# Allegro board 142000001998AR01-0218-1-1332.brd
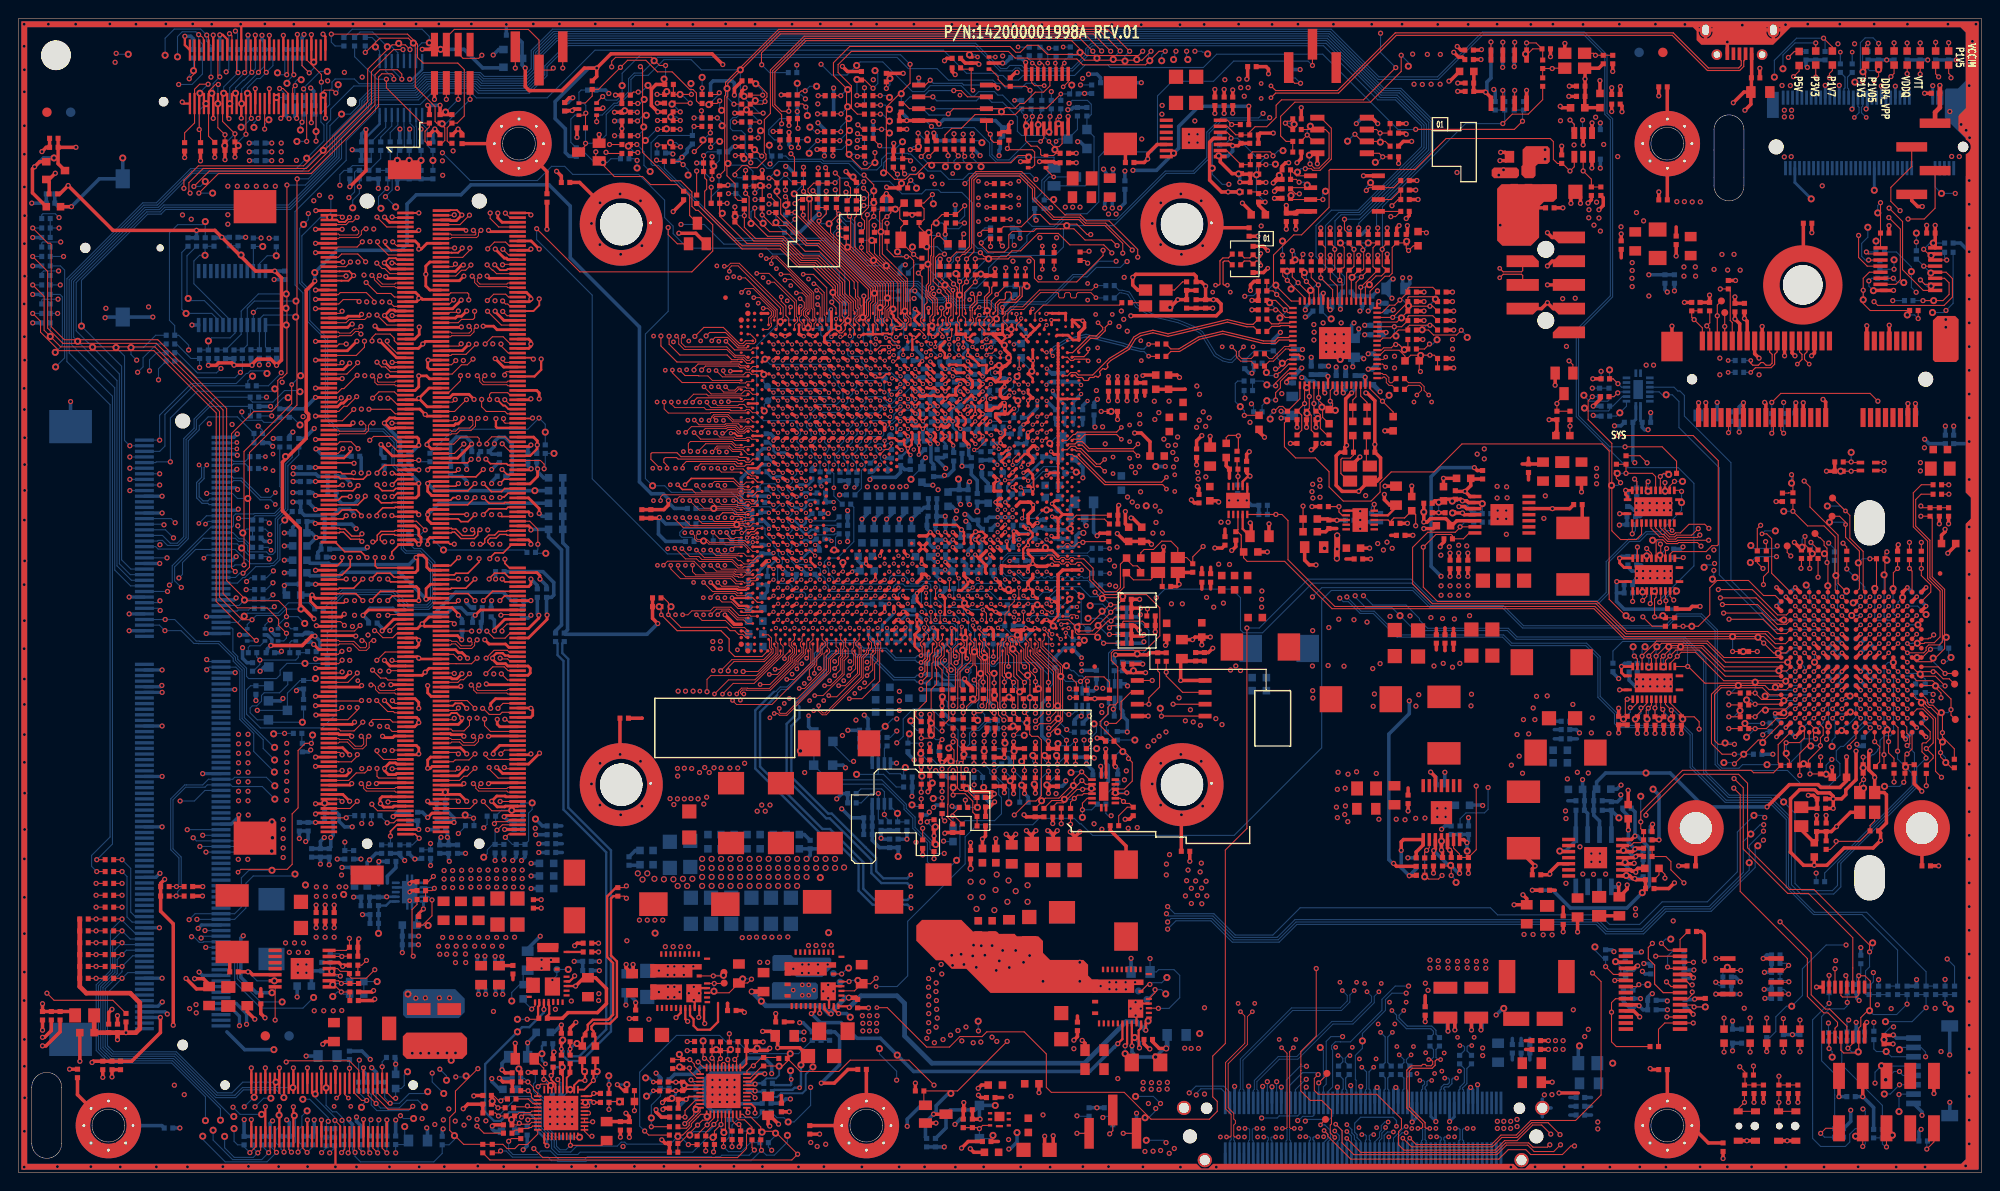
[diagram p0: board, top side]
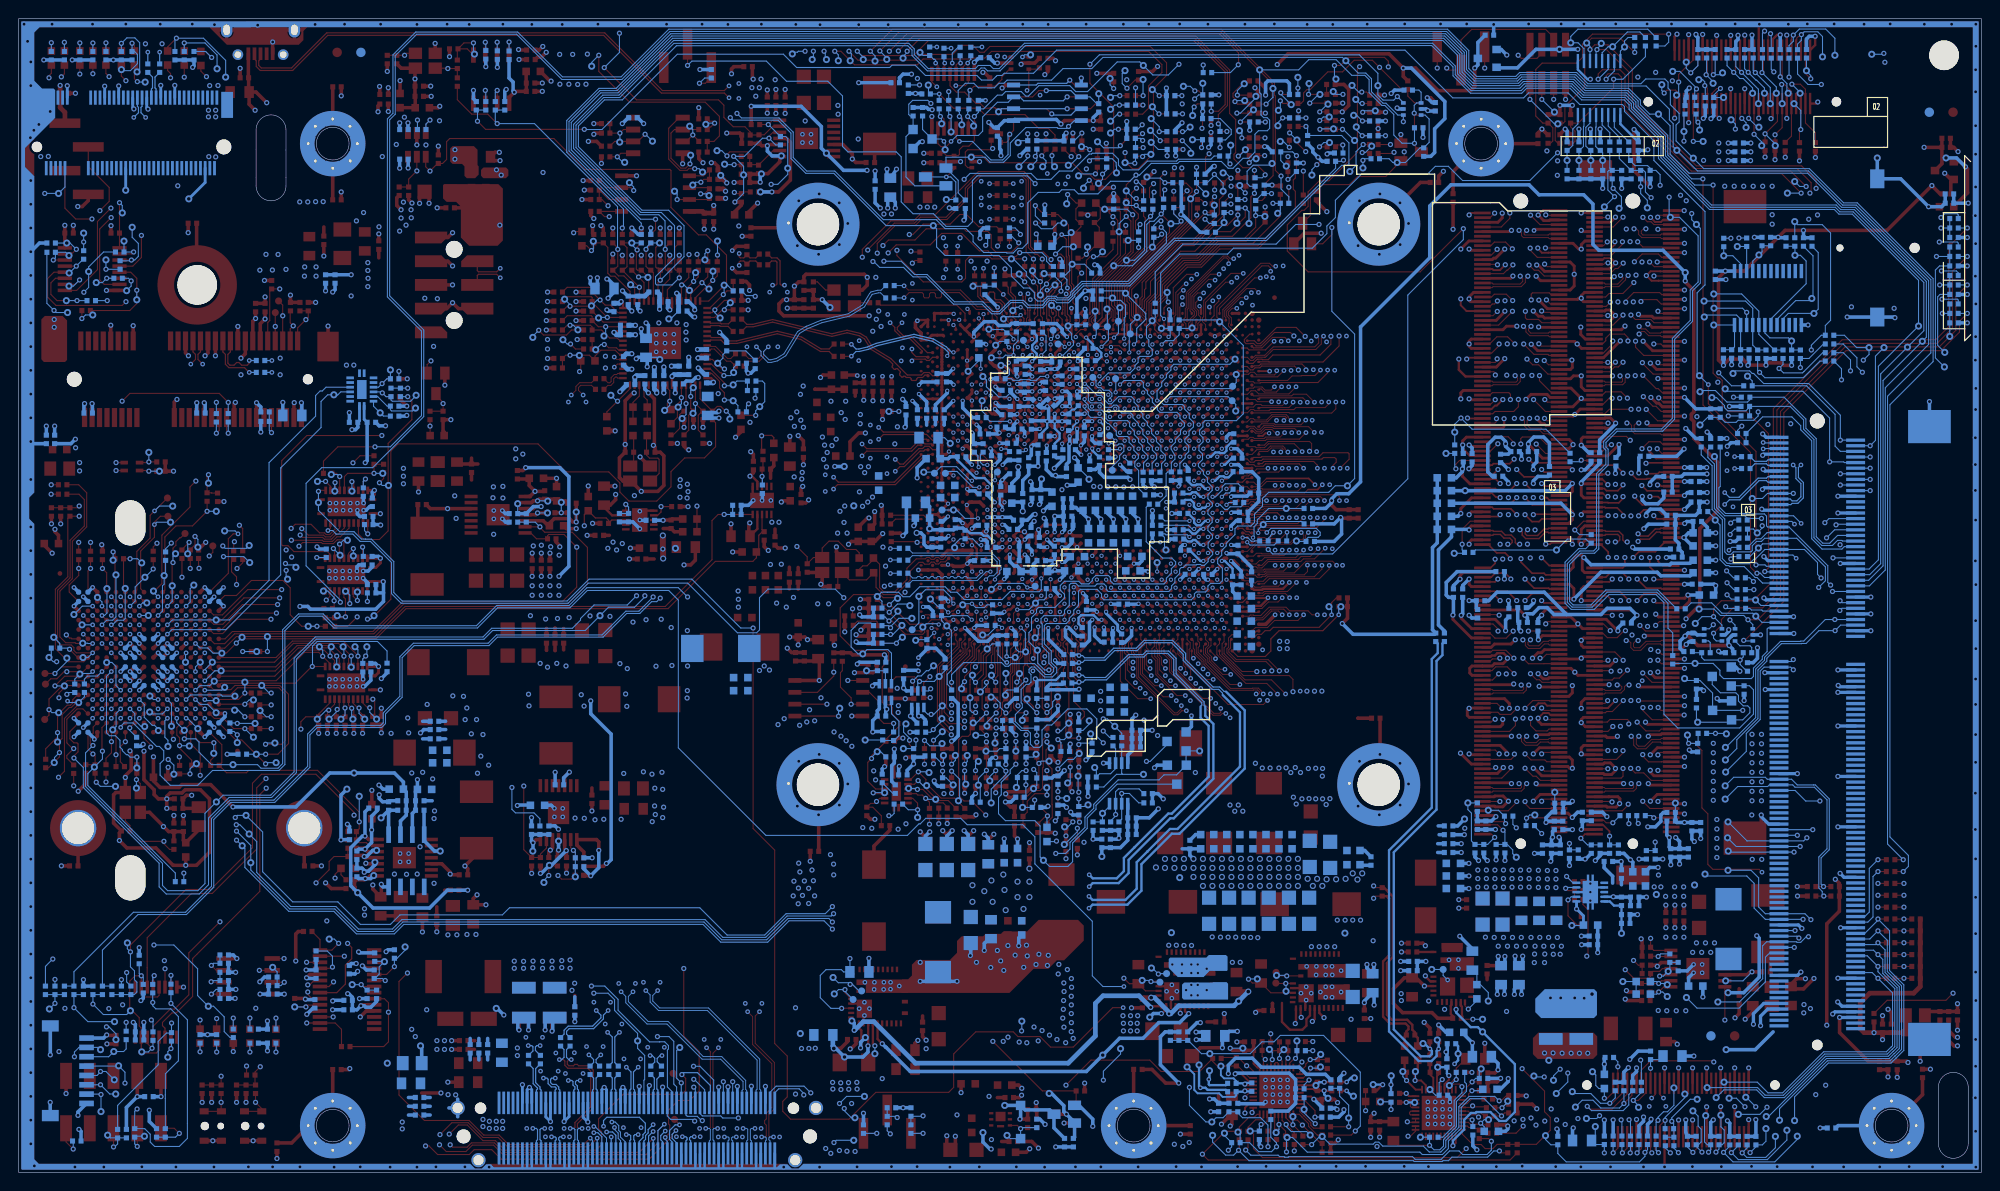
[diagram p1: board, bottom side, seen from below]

Outline 210 x 123.5 mm; copper layers: TOP, G2, S3, G4, S5, V6, V7, S8, G9, S10, G11, BOTTOM. Coordinates in mm from the lower left corner of the outline.
Outline path: 0,123.5 0,0 210,0 210,123.5 0,123.5 ; 1.4,9.1 1.4,3.1 arc(3,1.5) 4.6,3.1 4.6,9.1 arc(3,10.7) 1.4,9.1 ; 7.85,5 arc(9.6,6.75) 11.35,5 arc(9.6,3.25) 7.85,5 ; 51.78,110.12 arc(53.87,111.84) 55.14,109.45 arc(53.53,108.37) 51.91,109.45 arc(51.81,109.78) 51.78,110.12 ; 62.22,101.5 arc(64.47,103.75) 66.73,101.5 arc(64.47,99.25) 62.22,101.5 ; 62.22,41.5 arc(64.47,43.75) 66.73,41.5 arc(64.47,39.25) 62.22,41.5 ; 88.95,5 arc(90.7,6.75) 92.45,5 arc(90.7,3.25) 88.95,5 ; 122.23,101.5 arc(124.47,103.75) 126.72,101.5 arc(124.47,99.25) 122.23,101.5 ; 122.23,41.5 arc(124.47,43.75) 126.72,41.5 arc(124.47,39.25) 122.23,41.5 ; 174.65,5 arc(176.4,6.75) 178.15,5 arc(176.4,3.25) 174.65,5 ; 174.79,109.45 arc(176.06,111.84) 178.15,110.12 arc(178.12,109.78) 178.02,109.45 arc(176.4,108.37) 174.79,109.45 ; 177.75,36.85 arc(179.45,38.55) 181.15,36.85 arc(179.45,35.15) 177.75,36.85 ; 181.4,111.6 arc(183,113.2) 184.6,111.6 184.6,105.6 arc(183,104) 181.4,105.6 181.4,111.6 ; 188.8,95 arc(190.9,97.1) 193,95 arc(190.9,92.9) 188.8,95 ; 196.45,70.32 arc(198.05,71.92) 199.65,70.32 199.65,68.72 arc(198.05,67.12) 196.45,68.72 196.45,70.32 ; 196.45,32.32 arc(198.05,33.92) 199.65,32.32 199.65,30.72 arc(198.05,29.12) 196.45,30.72 196.45,32.32 ; 201.95,36.85 arc(203.65,38.55) 205.35,36.85 arc(203.65,35.15) 201.95,36.85

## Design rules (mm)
net group DIFF_10G_KR_C_RX0_: nets 10G_KR_C_RX0_N 10G_KR_C_RX0_P
net group DIFF_10G_KR_C_RX1_: nets 10G_KR_C_RX1_N 10G_KR_C_RX1_P
net group DIFF_10G_KR_RX0_: nets 10G_KR_RX0_N 10G_KR_RX0_P
net group DIFF_10G_KR_RX1_: nets 10G_KR_RX1_N 10G_KR_RX1_P
net group DIFF_10G_KR_TX0_: nets 10G_KR_TX0_N 10G_KR_TX0_P
net group DIFF_10G_KR_TX1_: nets 10G_KR_TX1_N 10G_KR_TX1_P
net group DIFF_CLK_100M_XDPCPU_: nets CLK_100M_XDPCPU_N CLK_100M_XDPCPU_P
net group DIFF_CLK_100M_XDPCPU_R_: nets CLK_100M_XDPCPU_R_N CLK_100M_XDPCPU_R_P
net group DIFF_CS1_VDDQ_CH01: nets CSN1_VDDQ_CH01 CSP1_VDDQ_CH01
net group DIFF_CS1_VDDQ_CH01_R: nets CSN1_VDDQ_CH01_R CSP1_VDDQ_CH01_R
net group DIFF_DDR0_CLK_D_1: nets DDR0_CLK_DN_1 DDR0_CLK_DP_1
net group DIFF_DDR0_CLK_D_3: nets DDR0_CLK_DN_3 DDR0_CLK_DP_3
net group DIFF_DDR1_CLK_D_1: nets DDR1_CLK_DN_1 DDR1_CLK_DP_1
net group DIFF_DDR1_CLK_D_3: nets DDR1_CLK_DN_3 DDR1_CLK_DP_3
net group DIFF_MAC_SGMII_RX_: nets MAC_SGMII_RX_N MAC_SGMII_RX_P
net group DIFF_MAC_SGMII_TX_: nets MAC_SGMII_TX_N MAC_SGMII_TX_P
net group DIFF_MGMT_MAC_RX0: nets PCIE2_MGMT_MAC_RX0_N_R PCIE2_MGMT_MAC_RX0_P_R
net group DIFF_PCIE2_MGMT_MAC_RX0_: nets PCIE2_MGMT_MAC_RX0_N PCIE2_MGMT_MAC_RX0_P
net group DIFF_PCIE2_MGMT_MAC_TX0_: nets PCIE2_MGMT_MAC_TX0_N PCIE2_MGMT_MAC_TX0_P
net group DIFF_PCIE3_100G_C_TX_D_0: nets PCIE3_100G_C_TX_DN_0 PCIE3_100G_C_TX_DP_0
net group DIFF_PCIE3_100G_C_TX_D_1: nets PCIE3_100G_C_TX_DN_1 PCIE3_100G_C_TX_DP_1
net group DIFF_PCIE3_100G_C_TX_D_2: nets PCIE3_100G_C_TX_DN_2 PCIE3_100G_C_TX_DP_2
net group DIFF_PCIE3_100G_C_TX_D_3: nets PCIE3_100G_C_TX_DN_3 PCIE3_100G_C_TX_DP_3
net group DIFF_PCIE3_100G_RX_D_0: nets PCIE3_100G_RX_DN_0 PCIE3_100G_RX_DP_0
net group DIFF_PCIE3_100G_RX_D_1: nets PCIE3_100G_RX_DN_1 PCIE3_100G_RX_DP_1
net group DIFF_PCIE3_100G_RX_D_2: nets PCIE3_100G_RX_DN_2 PCIE3_100G_RX_DP_2
net group DIFF_PCIE3_100G_RX_D_3: nets PCIE3_100G_RX_DN_3 PCIE3_100G_RX_DP_3
net group DIFF_PCIE3_100G_TX_D_0: nets PCIE3_100G_TX_DN_0 PCIE3_100G_TX_DP_0
net group DIFF_PCIE3_100G_TX_D_1: nets PCIE3_100G_TX_DN_1 PCIE3_100G_TX_DP_1
net group DIFF_PCIE3_100G_TX_D_2: nets PCIE3_100G_TX_DN_2 PCIE3_100G_TX_DP_2
net group DIFF_PCIE3_100G_TX_D_3: nets PCIE3_100G_TX_DN_3 PCIE3_100G_TX_DP_3
net group DIFF_PCIE_BMM_RX_: nets PCIE_BMM_RX_N PCIE_BMM_RX_P
net group DIFF_PCIE_BMM_TX_: nets PCIE_BMM_TX_N PCIE_BMM_TX_P
net group DIFF_PCIE_BMM_TX_C_: nets PCIE_BMM_TX_C_N PCIE_BMM_TX_C_P
net group DIFF_PCIE_CLK_B2B_CONN: nets PCIE_CLK_B2B_CONN_N PCIE_CLK_B2B_CONN_P
net group DIFF_PCIE_CLK_BMM_: nets PCIE_CLK_BMM_N PCIE_CLK_BMM_P
net group DIFF_PCIE_CLK_MAC: nets PCIE_CLK_MAC_N_R PCIE_CLK_MAC_P_R
net group DIFF_PCIE_CLK_MAC_: nets PCIE_CLK_MAC_N PCIE_CLK_MAC_P
net group DIFF_PCIE_CLK_R_B2B_CONN: nets PCIE_CLK_R_B2B_CONN_N PCIE_CLK_R_B2B_CONN_P
net group DIFF_PCIE_CLK_R_BMM_: nets PCIE_CLK_R_BMM_N PCIE_CLK_R_BMM_P
net group DIFF_PCIE_OOB_RX_: nets PCIE_OOB_RX_N PCIE_OOB_RX_P
net group DIFF_PCIE_OOB_TX_: nets PCIE_OOB_TX_N PCIE_OOB_TX_P
net group DIFF_PCIE_OOB_TX_C_: nets PCIE_OOB_TX_C_N PCIE_OOB_TX_C_P
net group DIFF_PD_CPU_TSTCLK_D: nets PD_CPU_TSTCLK_DN PD_CPU_TSTCLK_DP
net group DIFF_PD_TSTCLK_SC_D: nets PD_TSTCLK_SC_DN PD_TSTCLK_SC_DP
net group DIFF_RP_1.05V_R_SENSE_: nets RP_1.05V_R_SENSE_N RP_1.05V_R_SENSE_P
net group DIFF_RP_1.05V_SENSE_: nets RP_1.05V_SENSE_N RP_1.05V_SENSE_P
net group DIFF_RP_1.8V_SENSE_: nets RP_1.8V_SENSE_N RP_1.8V_SENSE_P
net group DIFF_RP_1.8V_SENSE__R: nets RP_1.8V_SENSE_N_R RP_1.8V_SENSE_P_R
net group DIFF_RP_CLKIN_GND_1_: nets RP_CLKIN_GND_1_N RP_CLKIN_GND_1_P
net group DIFF_RP_CLKIN_GND_2_: nets RP_CLKIN_GND_2_N RP_CLKIN_GND_2_P
net group DIFF_RP_CLKIN_GND_3_: nets RP_CLKIN_GND_3_N RP_CLKIN_GND_3_P
net group DIFF_RP_CLKIN_GND_4: nets RP_CLKIN_GND_N4 RP_CLKIN_GND_P4
net group DIFF_SATA3_C_RX0_: nets SATA3_C_RX0_N SATA3_C_RX0_P
net group DIFF_SATA3_C_RX1_: nets SATA3_C_RX1_N SATA3_C_RX1_P
net group DIFF_SATA3_C_TX0_: nets SATA3_C_TX0_N SATA3_C_TX0_P
net group DIFF_SATA3_C_TX1_: nets SATA3_C_TX1_N SATA3_C_TX1_P
net group DIFF_SATA3_RX0_: nets SATA3_RX0_N SATA3_RX0_P
net group DIFF_SATA3_RX1_: nets SATA3_RX1_N SATA3_RX1_P
net group DIFF_SATA3_TX0_: nets SATA3_TX0_N SATA3_TX0_P
net group DIFF_SATA3_TX1_: nets SATA3_TX1_N SATA3_TX1_P
net group DIFF_SGM_RX: nets MAC_SGMII_RX_N_R MAC_SGMII_RX_P_R
net group DIFF_TP_PE_HSCLK_D: nets TP_PE_HSCLK_DN TP_PE_HSCLK_DP
net group DIFF_TP_TEST_PE_DFX_D: nets TP_TEST_PE_DFX_DN TP_TEST_PE_DFX_DP
net group DIFF_TP_USB2_PLLMON_D: nets TP_USB2_PLLMON_DN TP_USB2_PLLMON_DP
net group DIFF_USB2_DEBUG_D: nets USB2_DEBUG_DN USB2_DEBUG_DP
net group DIFF_USB2_EUSB_D: nets USB2_EUSB_DN USB2_EUSB_DP
net group DIFF_USB2_FRONT_D: nets USB2_FRONT_DN USB2_FRONT_DP
net group DIFF_VDDQ_CPU_SEN_: nets VDDQ_CPU_SEN_N VDDQ_CPU_SEN_P
net group DIFF_VDDQ_CPU_SEN__R: nets VDDQ_CPU_SEN_N_R VDDQ_CPU_SEN_P_R
net group DIFF_VDDQ_TSEN_: nets VDDQ_TSEN_N VDDQ_TSEN_P
net group PCIE2_MGMT_MAC_C_TX0_: nets PCIE2_MGMT_MAC_C_TX0_N PCIE2_MGMT_MAC_C_TX0_P
net group PCIE_CLK_R_MAC_: nets PCIE_CLK_R_MAC_N PCIE_CLK_R_MAC_P
net group USB2: nets USB2_DN_3 USB2_DP_3
net group CLS_CLK: nets 1PPS_CPU BIOS_SPI_C_CLK BIOS_SPI_CLK BIOS_SPI_CLK_R CLK_33M_BMM CLK_33M_BMM_R CLK_33M_CPLD CLK_33M_LPC CLK_33M_LPC_PORT80 CLK_33M_LPC_TPM CLK_33M_R_CPLD CLK_33M_R_LPC CLK_33M_R_TPM CLK_33M_TPM CLK_50M CLK_50M_R CLK_BUF_50M_BMM CLK_BUF_50M_BMM_R CLK_M2_SUSCLK CPLD_CLK_25M CPLD_CLK_25M_R NIC1_NCSI_CLKIN_R RP_LPC_LCLK RP_LPC_R_LCLK RP_SVID_R_CLK SPI_10GBE_CLK SPI_10GBE_CLK_LVC3V3 SPI_10GBE_CLK_LVC3V3_R SPI_10GBE_CLK_R SVID_CLK SVID_CLK_DDR_R SVID_CLK_VCORE
net group CLS_DDR_POWER: nets P1V2_VDDQ
net group CLS_POWER: nets AGND_V3P3A DDR4_VPP_SW GND_SCREW1 GND_SCREW2 GND_SCREW3 GND_SCREW4 GND_SCREW5 P1V05_PCH_FLT P3V3_STBY_CLKBUF P3V3_STBY_OSC P5V_B P5V_CONN PS_12V_LVIN3 RP_3.3V_LVCC SW_VDDQ_CH01 V1P5_FB V1P5_SS V1P8A_EN V1P35_FB V1P35_SS V3P3_EN V3P3_PCH_EN V3P3_PCH_EN_N V3P3_R V3P3_SF100 V3P3_SPI V3P3_SS V3P3_SW V3P3_VBST V3P3_VREG V3P3A_EN V3P3A_R V3P3A_SS V3P3A_VBST V3P3A_VREG V5A_SS V5A_SW V5A_VBST V5A_VO V5A_VREG V12A_V5A VCC_EUSB VCCAXCK_DCB VCCGBE_FLT VCCIN_P1V05_VCC
net group CLS_S12: nets MAC_MDC0 RP_DDR_R_I2C_SCL SMB_9548_SCL0 SMB_9548_SCL1 SMB_PCU_CLK_P3V3 SMB_PCU_CLK_P3V3_SWITCH_R SUSCLK_32K_CPLD
net group XDP_CPU_MBP: nets XDP_CPU_MBP<2> XDP_CPU_MBP<3> XDP_CPU_MBP<4> XDP_CPU_MBP<5> XDP_CPU_MBP<6> XDP_CPU_MBP<7>

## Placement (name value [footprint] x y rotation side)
BA1  AAA-BAT-046-K03  [BATTERY_14D8_2SP_15D5W10D39L]  11.13 98.96 270 bottom
C1  0.1uF/10V  [CC0402]  185.85 117.17 90 top
C2  22uF/16V  [CC0805]  186.36 115.65 90 top
C3  0.1uF  [CC0402]  175.94 116.2 270 top
C4  100uF/6.3V  [CC1206]  123.83 115.88 0 top
C5  100uF/6.3V  [CC1206]  125.99 115.88 0 top
C6  1uF/6.3V  [CC0402]  170.91 114.35 90 top
C7  0.1uF/16V  [CC0402]  170.91 115.4 90 top
C8  10uF/6.3V  [CC0402]  127.99 114.66 0 top
C9  10nF/50V  [CC0402]  128.98 114.66 180 top
C10  0.1uF/16V  [CC0402]  129.9 114.66 180 top
C11  0.1uF/16V  [CC0402]  58.43 114.07 180 top
C12  0.1uF  [CC0402]  191.41 101.6 90 top
C13  0.1uF/16V  [CC0402]  94.23 112.12 0 top
C14  1uF/6.3V  [CC0402]  3.76 110.69 90 top
C15  0.1uF  [CC0402]  47.44 110.58 180 top
C16  0.1uF/16V  [CC0402]  155.19 119.13 90 top
C17  1uF/6.3V  [CC0402]  155.19 120.14 90 top
C18  0.1uF/16V  [CC0402]  155.23 115.72 270 top
C19  1uF/6.3V  [CC0402]  155.23 116.61 270 top
C20  1uF/6.3V  [CC0402]  132.18 110.16 90 top
C21  1uF/6.3V  [CC0402]  3.76 109.73 90 top
C22  @10pF  [CC0402]  163.45 120.27 270 top
C23  0.1uF/25V  [CC0402]  118.87 108.1 90 top
C24  10pF/50V  [CC0402]  130.84 107.37 180 top
C25  0.1uF  [CC0402]  131.65 100.66 180 top
C26  10nF  [CC0402]  104.85 105.84 270 top
C27  22uF/16V  [CC0805]  116.74 105.41 0 top
C28  22uF/16V  [CC0805]  116.74 105.41 180 bottom
C29  0.1uF/16V  [CC0402]  118.36 105.69 180 bottom
C30  0.1uF/16V  [CC0402]  183.64 92.57 180 top
C31  0.1uF/16V  [CC0402]  184.65 92.57 180 top
C32  10nF  [CC0402]  104.85 104.57 270 top
C33  22uF/16V  [CC0805]  113.77 104.39 90 top
C34  3300pF  [CC0402]  132.67 104.32 0 top
C35  0.1uF  [CC0402]  56.52 104.31 0 top
C36  0.1uF  [CC0402]  175.95 104.1 270 top
C37  10nF  [CC0402]  104.85 103.3 270 top
C38  15pF  [CC0402]  94.9 102.13 180 top
C39  15pF  [CC0402]  96.34 102.13 180 top
C40  10nF  [CC0402]  104.85 102.03 270 top
C41  @10pF  [CC0402]  161.04 114.17 0 bottom
C42  0.1uF  [CC0402]  124.85 34.37 270 top
C51  0.1uF  [CC0402]  125.98 94.87 180 top
C52  0.1uF  [CC0402]  127 92.96 180 top
C54  0.1uF/16V  [CC0402]  202.56 81.28 90 bottom
C55  1uF/6.3V  [CC0402]  192.89 39.98 90 top
C57  0.22uF  [CC0402]  122.3 88.67 90 top
C58  0.1uF/16V  [CC0402]  190.5 81.28 90 bottom
C59  0.1uF/16V  [CC0402]  192.89 38.96 90 top
C60  0.22uF  [CC0402]  122.3 87.35 90 top
C61  22uF/16V  [CC0805]  180.72 81.03 270 bottom
C63  22uF6.3V  [CC0603]  205.62 77.37 270 top
C64  1uF/6.3V  [CC0402]  206.15 78.46 180 bottom
C65  0.1uF/16V  [CC0402]  207.04 78.46 180 bottom
C66  1uF/6.3V  [CC0402]  192.38 36.93 180 top
C67  0.1uF/16V  [CC0402]  193.4 36.93 180 top
C68  22uF/6.3V  [CC0603]  121.67 84.59 0 top
C69  22uF/6.3V  [CC0603]  123.04 84.59 0 top
C70  22uF/6.3V  [CC0603]  192.13 34.52 0 top
C74  1uF/6.3V  [CC0402]  120.49 84.07 0 top
C75  1uF/6.3V  [CC0402]  119.58 84.07 0 top
C76  0.1uF/16V  [CC0402]  117.57 84.07 0 top
C77  0.1uF/16V  [CC0402]  118.59 84.07 0 top
C78  0.1uF/16V  [CC0402]  116.61 84.07 0 top
C81  4.7uF/6.3V  [CC0603]  149.06 71.58 0 top
C82  10uF/6.3V  [CC0402]  147.87 68.19 90 top
C83  22uF/6.3V  [CC0603]  206.5 67.31 90 top
C84  22uF/16V  [CC0805]  147.37 72.44 180 top
C87  0.1uF/16V  [CC0402]  126.03 76.99 0 top
C88  47uF/6.3V  [CC0805]  127.49 76.62 180 top
C89  680pF/50V  [CC0402]  131.39 75.66 180 top
C90  @0.1uF/16V  [CC0402]  130 75.28 270 top
C91  0.1uF/16V  [CC0402]  143.35 65.66 90 top
C92  22uF/6.3V  [CC0603]  142.82 66.82 90 top
C93  22uF/6.3V  [CC0603]  127.45 72.65 0 top
C94  0.1uF/16V  [CC0402]  126.29 72.12 0 top
C95  @0.1uF/16V  [CC0402]  140.19 69.37 0 top
C96  680pF/50V  [CC0402]  139.68 71.27 270 top
C97  47uF/6.3  [CC0805]  138.62 66.93 270 top
C98  0.1uF  [CC0402]  66.67 70.48 0 top
C99  22uF/16V  [CC0805]  132.77 68.1 90 top
C100  0.1uF/16V  [CC0402]  171.2 48.36 180 top
C101  10uF/6.3V  [CC0402]  129.07 67.59 0 top
C102  4.7uF/6.3V  [CC0603]  131.83 66.41 270 top
C103  12pF/1%  [CC0402]  125.63 64.69 0 top
C104  1uF/6.3V  [CC0402]  126.6 63.63 180 top
C105  1uF/6.3V  [CC0402]  127.54 63.63 180 top
C106  47uF  [CC0603]  128.73 63.12 180 top
C107  47uF  [CC0603]  130.1 63.12 180 top
C108  12pF/1%  [CC0402]  122.81 62.71 90 top
C109  22uF/6.3V  [CC0603]  194.82 42.29 270 top
C110  0.1uF/25V  [CC0402]  162.41 31.85 90 top
C111  22uF/16V  [CC0805]  124.46 56.01 180 top
C112  0.1uF/16V  [CC0402]  125.93 55.19 180 top
C113  1uF/ 6.3V  [CC0402]  126.87 55.19 180 top
C114  0.1uF/16V  [CC0402]  118.65 54.41 270 top
C115  22uF/6.3V  [CC0603]  164.95 43.84 270 bottom
C116  22uF/6.3V  [CC0603]  164.95 45.19 270 bottom
C117  10uF/6.3V  [CC0402]  165.51 46.41 270 bottom
C118  0.1uF/16V  [CC0402]  165.26 27 0 top
C119  10nF/50V  [CC0402]  165.51 47.4 90 bottom
C120  0.1uF/16V  [CC0402]  165.51 48.29 90 bottom
C121  22uF/16V  [CC0805]  166.8 28.35 0 top
C123  22uF/16V  [CC0805]  171.27 28.47 180 top
C124  0.1uF  [CC0402]  58.52 105.97 90 top
C125  220uF/4V  [CAP_6D4_2SP_4D3W7D3L2D1H]  87.78 45.92 0 top
C126  0.1uF  [CC0402]  204.1 32.81 90 top
C127  0.1uF  [CC0402]  178.97 32.8 270 top
C128  0.1uF/16V  [CC0402]  116.76 44.48 90 top
C129  3300pF  [CC0402]  174.32 34.7 270 top
C130  @10pF/50V  [CC0402]  136.78 112.78 90 top
C131  220uF/4V  [CAP_6D4_2SP_4D3W7D3L2D1H]  76.23 38.45 270 top
C132  220uF/4V  [CAP_6D4_2SP_4D3W7D3L2D1H]  81.56 38.45 270 top
C133  220uF/4V  [CAP_6D4_2SP_4D3W7D3L2D1H]  86.79 38.45 270 top
C134  100uF/6.3V  [CC1206]  71.75 37.24 180 top
C135  100uF/6.3V  [CC1206]  161.08 64.74 180 top
C136  100uF/6.3V  [CC1206]  158.84 64.74 180 top
C137  100uF/6.3V  [CC1206]  156.67 64.74 180 top
C138  0.1uF  [CC0402]  64.79 48.61 270 top
C139  0.1uF  [CC0402]  102.49 65.48 90 bottom
C140  10uF/6.3V  [CC0402]  154.08 65.07 180 top
C141  10nF/50V  [CC0402]  153.16 65.07 0 top
C142  0.1uF/16V  [CC0402]  155.06 65.07 0 top
C143  22uF/6.3V  [CC0603]  104.55 33.9 180 top
C144  22uF/6.3V  [CC0603]  104.16 26.17 0 top
C145  22uF/6.3V  [CC0603]  102.68 26.17 0 top
C146  22uF/6.3V  [CC0603]  103.12 33.9 180 top
C147  47uF/6.3V  [CC0805]  106.25 34.05 180 top
C148  47uF/6.3V  [CC0805]  105.96 26.02 0 top
C149  100uF/6.3V  [CC1206]  108.13 25.93 0 top
C150  100uF/6.3V  [CC1206]  108.41 33.76 180 top
C151  100uF/6.3V  [CC1206]  110.69 33.76 180 top
C152  100uF/6.3V  [CC1206]  112.98 33.76 180 top
C153  10uF/6.3V  [CC0402]  199.59 14.2 0 top
C154  0.1uF/16V  [CC0402]  144.27 112.9 90 bottom
C155  0.1uF/16V  [CC0402]  43.08 31.11 90 top
C156  3300pF  [CC0402]  150.8 70.61 270 top
C157  220uF/4V  [CAP_6D4_2SP_4D3W7D3L2D1H]  98.42 28.68 90 top
C158  1nF/50V  [CC0402]  150.5 17.27 0 top
C159  0.1uF/16V  [CC0402]  166.84 71.48 270 top
C160  10pF  [CC0402]  153.72 72.52 0 top
C161  47uF/6.3V  [CC0805]  45.46 28 180 top
C162  47uF/6.3V  [CC0805]  47.32 27.99 180 top
C163  47uF/6.3V  [CC0805]  49.21 27.99 180 top
C164  47uF/16V  [CC1210]  152.66 18.16 0 top
C165  100uF/6.3V  [CC1206]  51.23 27.91 0 top
C166  100uF/6.3V  [CC1206]  53.37 27.91 0 top
C167  220uF/4V  [CAP_6D4_2SP_4D3W7D3L2D1H]  27.05 26.04 90 bottom
C168  100uF/6.3V  [CC1206]  30.2 27.56 0 top
C169  10uF/6.3V  [CC0402]  31.83 27.36 0 top
C170  0.1uF/16V  [CC0402]  32.79 27.36 180 top
C171  10nF/50V  [CC0402]  33.76 27.36 180 top
C172  22uF/16V  [CC0805]  167.22 75.02 0 top
C173  22uF/16V  [CC0805]  163.1 75.02 180 top
C174  0.1uF/16V  [CC0402]  161.55 75.37 180 top
C175  47uF/16V  [CC1210]  155.96 18.16 0 top
C176  3300pF  [CC0402]  35.84 22.17 270 top
C177  0.1uF/16V  [CC0402]  52.88 21.69 0 top
C178  0.1uF/25V  [CC0402]  23.04 21.46 90 top
C179  0.22uF  [CC0805]  77.06 21.29 180 top
C180  0.22uF  [CC0805]  90.2 21.21 180 top
C181  22uF/16V  [CC0805]  49.48 21.11 0 top
C182  22uF/16V  [CC0805]  51.38 21.11 0 top
C183  0.1uF/16V  [CC0402]  151.69 57.1 0 top
C184  10nF/50V  [CC0402]  152.61 57.1 0 top
C185  10uF/6.3V  [CC0402]  153.53 57.1 180 top
C186  22uF/16V  [CC0805]  65.63 20.24 180 top
C187  100uF/6.3V  [CC1206]  147.23 56.66 180 top
C188  100uF/6.3V  [CC1206]  155.44 56.71 180 top
C189  10pF  [CC0402]  35.43 19.76 180 top
C190  22uF/16V  [CC0805]  20.37 18.87 180 top
C191  22uF/16V  [CC0805]  24.46 18.85 0 top
C192  0.1uF/16V  [CC0402]  25.91 18.49 0 top
C193  1uF/6.3V  [CC0402]  89.76 18.06 0 top
C194  1uF/6.3V  [CC0402]  76.3 17.32 90 top
C195  0.1uF/16V  [CC0402]  66.01 16.92 0 top
C196  1uF/6.3V  [CC0402]  2.55 16.76 0 top
C197  0.1uF/16V  [CC0402]  3.49 16.76 0 top
C198  10nF/50V  [CC0402]  4.43 16.76 180 top
C199  1uF/6.3V  [CC0402]  120.86 14.22 270 top
C200  0.1uF/16V  [CC0402]  81.46 16.1 270 top
C201  0.1uF/16V  [CC0402]  113.28 15.62 0 top
C202  47uF/16V  [CC1210]  42.81 15.88 0 top
C203  47uF/16V  [CC1210]  46.07 15.88 0 top
C204  0.1uF/16V  [CC0402]  9.63 15.41 180 top
C205  10nF/50V  [CC0402]  10.57 15.41 0 top
C206  22uF/16V  [CC0805]  33.73 15.01 0 top
C207  22uF/6.3V  [CC0603]  7.31 14.95 270 top
C208  22uF/16V  [CC0805]  115.11 13.08 270 top
C209  22uF/16V  [CC0805]  81.97 14.61 270 top
C210  0.1uF/16V  [CC0402]  162.38 14.1 90 top
C211  22uF/16V  [CC0805]  147.22 40.36 0 top
C212  0.1uF/16V  [CC0402]  162.38 13.16 90 top
C213  @1nF  [CC0402]  77.41 13.05 90 top
C214  @1nF  [CC0402]  72.78 13.03 90 top
C215  @1nF  [CC0402]  74.64 13.03 90 top
C216  0.1uF/16V  [CC0402]  148.67 39.93 0 top
C217  22uF/16V  [CC0805]  115.11 11.05 270 top
C218  22uF/16V  [CC0805]  54.15 12.15 270 top
C219  22uF/16V  [CC0805]  144.2 38.91 90 top
C220  100pF  [CC0402]  79.71 11.84 180 top
C221  0.1uF/16V  [CC0402]  57.18 11.71 180 top
C222  22uF/16V  [CC0805]  161.9 11.68 90 top
C223  100pF  [CC0402]  71.04 11.61 0 top
C224  10uF/6.3V  [CC0402]  9 11.44 0 top
C225  0.1uF/16V  [CC0402]  9.99 11.44 0 top
C226  10nF/50V  [CC0402]  10.89 11.44 180 top
C227  0.1uF  [CC0402]  90.25 11.01 270 top
C228  0.1uF  [CC0402]  175.95 11 270 top
C231  3300pF  [CC0402]  58.53 10.71 270 top
C232  220pF  [CC0402]  61.04 10.71 270 top
C233  0.1uF/16V  [CC0402]  55.73 10.7 270 top
C234  0.1uF  [CC0402]  6.29 10.59 180 top
C235  22uF/16V  [CC0805]  161.9 9.65 90 top
C236  22uF/6.3V  [CC0603]  104.5 9.34 270 top
C237  3300pF  [CC0402]  71.04 9.19 180 top
C238  10nF/50V  [CC0402]  53.26 8.74 270 top
C239  0.1uF/16V  [CC0402]  104.01 8 90 top
C240  1uF/6.3V  [CC0402]  81.61 6.94 180 top
C241  680pF  [CC0402]  101.58 6.7 270 top
C242  1uF/6.3V  [CC0402]  151.38 33.25 0 top
C243  3300pF  [CC0402]  153.28 33.25 180 top
C244  0.22uF  [CC0402]  141.22 10.92 180 bottom
C245  0.22uF  [CC0402]  142.37 10.92 180 bottom
C246  0.22uF  [CC0402]  151 13.97 180 bottom
C247  0.22uF  [CC0402]  152.02 13.97 180 bottom
C248  0.1uF  [CC0402]  70.11 5.91 90 top
C249  0.1uF/16V  [CC0402]  101.07 5.24 0 top
C250  0.1uF/16V  [CC0402]  64.38 4.97 0 top
C251  10uF/6.3V  [CC0402]  65.34 4.97 0 top
C252  1uF  [CC0402]  189.36 8.89 0 top
C253  0.1uF  [CC0402]  84.64 4.55 0 top
C254  10nF/50V  [CC0402]  52.32 5.08 270 top
C255  0.01uF  [CC0402]  77.25 3.96 180 top
C256  0.1uF/16V  [CC0402]  103.57 3.3 90 top
C257  0.1uF  [CC0402]  182.37 2.69 0 top
C258  0.01uF  [CC0402]  70.08 2.15 90 top
C259  22uF/6.3V  [CC0603]  104.09 2.15 270 top
C260  0.1uF/16V  [CC0402]  52.63 121.74 90 bottom
C262  0.1uF/16V  [CC0402]  58.43 114.07 0 bottom
C263  0.1uF/16V  [CC0402]  105.28 111.38 180 bottom
C264  0.1uF/10V  [CC0402]  163.83 103.25 90 top
C265  22uF/16V  [CC0805]  160.53 108.71 270 top
C266  22uF/6.3V  [CC0603]  166.81 113.96 270 top
C267  0.1uF/16V  [CC0402]  25.91 110.19 90 bottom
C268  1uF/6.3V  [CC0402]  167.14 115.19 270 top
C269  1uF/6.3V  [CC0402]  25.91 109.25 90 bottom
C270  0.1uF/16V  [CC0402]  167.14 116.28 270 top
C271  10uF/6.3V  [CC0402]  25.91 108.31 90 bottom
C272  1uF/6.3V  [CC0402]  3.41 104.74 270 bottom
C273  1uF/6.3V  [CC0402]  3.41 103.75 270 bottom
C274  1uF/6.3V  [CC0402]  100.23 102.08 0 bottom
C275  @10pF  [CC0402]  157.99 114.17 0 bottom
C276  10nF  [CC0402]  184.12 86.91 270 bottom
C277  10nF  [CC0402]  184.12 85.64 270 bottom
C278  0.1uF/16V  [CC0402]  28.45 96.03 180 bottom
C279  560uF/2V  [CAP_6D4_2SP_4D3W7D3L4D3H]  111.63 24.64 90 bottom
C280  220uF/4V  [CAP_6D4_2SP_4D3W7D3L2D1H]  143.61 50.65 0 top
C281  10nF  [CC0402]  194.92 118.2 180 bottom
C282  10nF  [CC0402]  196.19 118.2 180 bottom
C283  0.1uF/16V  [CC0402]  177.35 99.77 180 top
C284  0.1uF/16V  [CC0402]  171.47 99.26 0 top
C285  @1uF  [CC0402]  86.79 90.81 180 bottom
C286  0.1uF  [CC0402]  101.45 90.4 180 bottom
C287  22uF/16V  [CC0805]  161.36 27.63 180 top
C288  0.1uF  [CC0402]  131.95 118.36 90 top
C289  0.1uF  [CC0402]  95.51 88.21 270 bottom
C290  0.1uF  [CC0402]  177.16 95.63 180 bottom
C291  0.1uF  [CC0402]  116.21 116.65 270 bottom
C292  0.1uF  [CC0402]  95.25 86.89 270 bottom
C293  0.1uF  [CC0402]  99.01 86.74 90 bottom
C294  0.1uF  [CC0402]  103.25 86.38 180 bottom
C295  0.1uF  [CC0402]  100.65 86.36 180 bottom
C296  0.1uF  [CC0402]  102.31 85.88 180 bottom
C297  0.1uF/16V  [CC0402]  96.77 85.55 180 bottom
C298  0.1uF  [CC0402]  176.15 95.63 180 bottom
C299  0.1uF/16V  [CC0402]  110.72 85.07 180 bottom
C300  0.1uF/16V  [CC0402]  111.74 85.07 180 bottom
C301  @1uF  [CC0402]  104.9 84.96 90 bottom
C302  0.1uF/16V  [CC0402]  98.35 84.81 0 bottom
C303  0.1uF  [CC0402]  100.13 84.15 180 bottom
C304  0.1uF  [CC0402]  102.39 83.94 180 bottom
C305  1uF/6.3V  [CC0402]  104.32 83.72 90 bottom
C306  0.1uF  [CC0402]  97.97 82.88 90 bottom
C307  0.1uF/16V  [CC0402]  96.62 82.53 0 bottom
C308  1uF/6.3V  [CC0402]  99.55 82.4 315 bottom
C309  0.1uF/16V  [CC0402]  101.14 82.39 135 bottom
C310  1uF/6.3V  [CC0402]  103.43 81.99 90 bottom
C311  0.1uF/16V  [CC0402]  115.06 81.53 0 bottom
C312  0.1uF/16V  [CC0402]  97.15 81.18 90 bottom
C313  0.1uF/16V  [CC0402]  110.97 81.18 0 bottom
C314  0.1uF/16V  [CC0402]  111.91 81.18 0 bottom
C315  0.1uF/16V  [CC0402]  112.85 81.18 0 bottom
C316  0.1uF/16V  [CC0402]  113.84 81.18 0 bottom
C317  0.1uF/16V  [CC0402]  104.35 81.1 90 bottom
C318  0.1uF/16V  [CC0402]  172.26 80.29 90 bottom
C319  0.1uF/16V  [CC0402]  174.17 80.29 270 bottom
C320  1uF/6.3V  [CC0402]  101.65 80.01 0 bottom
C321  0.1uF/16V  [CC0402]  97.66 79.85 0 bottom
C322  0.1uF  [CC0402]  104.87 79.78 90 bottom
C323  0.1uF  [CC0402]  103.09 79.58 90 bottom
C324  0.1uF  [CC0402]  95.97 79.3 0 bottom
C325  0.1uF  [CC0402]  106.68 79.04 90 bottom
C326  1uF/6.3V  [CC0402]  100.2 78.82 270 bottom
C327  47uF  [CC0805]  112.65 78.64 90 bottom
C328  0.1uF/16V  [CC0402]  79.98 78.61 0 bottom
C329  0.1uF  [CC0402]  94.31 78.51 0 bottom
C330  0.1uF  [CC0402]  103.73 78.05 90 bottom
C331  0.1uF/16V  [CC0402]  96.93 77.82 0 bottom
C332  0.1uF/16V  [CC0402]  145.72 70.08 180 bottom
C333  0.1uF  [CC0402]  100.94 77.42 0 bottom
C334  1uF/6.3V  [CC0402]  99.16 77.16 0 bottom
C335  0.1uF/16V  [CC0402]  48.03 77.16 270 bottom
C336  0.1uF/16V  [CC0402]  49.88 77.16 270 bottom
C337  @1uF  [CC0402]  98.27 76.91 0 bottom
C338  0.1uF  [CC0402]  105.46 76.71 270 bottom
C339  0.1uF/16V  [CC0402]  36.04 76.65 90 bottom
C340  0.22uF  [CC0402]  25.2 76.62 90 bottom
C341  0.1uF  [CC0402]  100.05 76.61 0 bottom
C342  10nF  [CC0402]  109.11 76.6 270 bottom
C343  0.1uF/16V  [CC0402]  54.49 76.5 0 bottom
C344  10nF/50V  [CC0402]  55.43 76.5 0 bottom
C345  0.1uF/16V  [CC0402]  79.55 76.45 90 bottom
C346  0.1uF/16V  [CC0402]  51.44 76.42 0 bottom
C347  0.1uF/16V  [CC0402]  40.84 76.58 0 bottom
C348  10nF/50V  [CC0402]  41.75 76.58 0 bottom
C349  0.1uF  [CC0402]  94.36 76.12 0 bottom
C350  0.1uF/16V  [CC0402]  39.1 76.07 0 bottom
C351  0.1uF  [CC0402]  101.93 76.05 0 bottom
C352  0.1uF  [CC0402]  95.4 75.69 0 bottom
C353  10nF/50V  [CC0402]  30.6 75.45 90 bottom
C354  0.22uF  [CC0402]  25.2 75.35 90 bottom
C355  0.1uF/16V  [CC0402_22X22_8OCT]  188.59 61.61 0 bottom
C356  0.1uF/16V  [CC0402_22X22_8OCT]  203.59 61.61 0 bottom
C357  0.1uF/16V  [CC0402_22X22_8OCT]  189.59 61.61 180 bottom
C358  0.1uF/16V  [CC0402_22X22_8OCT]  202.59 61.61 180 bottom
C359  0.1uF/16V  [CC0402]  46.21 75.1 0 bottom
C360  0.1uF/16V  [CC0402]  79.6 75.01 90 bottom
C361  0.1uF/16V  [CC0402]  97.89 74.93 0 bottom
C362  0.1uF/16V  [CC0402]  103.5 74.78 90 bottom
C363  0.1uF/16V  [CC0402]  84.86 74.68 0 bottom
C364  10pF  [CC0402]  86.66 74.52 0 bottom
C365  10nF/50V  [CC0402]  51.66 74.52 270 bottom
C366  0.1uF  [CC0402]  87.88 74.5 0 bottom
C367  @1uF  [CC0402]  88.8 74.5 0 bottom
C368  1uF  [CC0402]  89.69 74.5 0 bottom
C369  0.1uF/16V  [CC0402]  33.52 74.49 90 bottom
C370  22uF/6.3V  [CC0603]  57.45 74.35 270 bottom
C371  0.1uF/16V  [CC0402]  30.6 73.95 90 bottom
C372  47uF/4V  [CC0603]  110.6 73.54 90 bottom
C373  22uF/6.3V  [CC0603]  57.45 72.97 270 bottom
C374  1uF/6.3  [CC0402]  104.92 72.95 180 bottom
C375  0.1uF/16V  [CC0402]  172.16 71.73 180 bottom
C376  0.1uF/16V  [CC0402]  33.52 72.82 90 bottom
C377  0.1uF/16V  [CC0402]  77.77 72.72 90 bottom
C378  0.1uF/16V  [CC0402]  85.88 72.72 270 bottom
C379  0.1uF  [CC0402]  106.78 72.63 90 bottom
C380  0.1uF/16V  [CC0402]  100.63 72.62 0 bottom
C381  10nF/50V  [CC0402]  101.58 72.62 0 bottom
C382  1uF  [CC0402]  89.03 72.52 270 bottom
C383  0.1uF/16V  [CC0402]  30.61 72.77 90 bottom
C384  47uF/4V  [CC0603]  110.6 72.24 90 bottom
C385  10uF/6.3V  [CC0402]  102.57 72.21 180 bottom
C386  0.1uF/16V  [CC0402]  97.79 72.11 270 bottom
C387  0.1uF/16V  [CC0402]  85.88 71.75 270 bottom
C388  47uF  [CC0805]  114 71.73 90 bottom
C389  22uF/6.3V  [CC0603]  57.45 71.63 270 bottom
C390  22uF/6.3V  [CC0603]  90.81 71.63 180 bottom
C391  22uF/6.3V  [CC0603]  92.12 71.63 180 bottom
C392  22uF/6.3V  [CC0603]  93.45 71.63 180 bottom
C393  22uF/6.3V  [CC0603]  94.79 71.63 180 bottom
C394  22uF/6.3V  [CC0603]  96.12 71.63 180 bottom
C395  10nF/50V  [CC0402]  30.61 71.75 90 bottom
C396  0.1uF/16V  [CC0402]  172.54 70.21 270 bottom
C397  10uF  [CC0402]  97.76 71.17 270 bottom
C398  0.1uF/16V  [CC0402_22X22_8OCT]  195.09 57.11 90 bottom
C399  0.1uF/16V  [CC0402_22X22_8OCT]  197.09 57.11 270 bottom
C400  0.1uF/16V  [CC0402]  78.92 70.66 90 bottom
C401  0.1uF/16V  [CC0402]  85.34 70.54 270 bottom
C402  0.1uF/16V  [CC0402]  133.15 70.43 90 bottom
C403  0.1uF/16V  [CC0402]  33.19 70.33 90 bottom
C404  1uF  [CC0402]  97.76 70.23 270 bottom
C405  22uF/6.3V  [CC0603]  57.45 70.23 270 bottom
C406  0.1uF/16V  [CC0402]  103.1 69.81 270 bottom
C407  0.1uF/16V  [CC0402]  78.92 69.77 90 bottom
C408  0.1uF/16V  [CC0402]  30.38 69.67 90 bottom
C409  0.1uF  [CC0402]  109.78 69.42 180 bottom
C410  10nF/50V  [CC0402]  33.19 69.39 90 bottom
C411  0.1uF/16V  [CC0402_22X22_8OCT]  193.59 55.61 0 bottom
C412  0.1uF/16V  [CC0402_22X22_8OCT]  194.59 55.61 0 bottom
C413  0.1uF/16V  [CC0402_22X22_8OCT]  197.59 55.61 0 bottom
C414  0.1uF/16V  [CC0402_22X22_8OCT]  198.59 55.61 0 bottom
C415  0.1uF/16V  [CC0402]  99.62 69.29 90 bottom
C416  0.1uF  [CC0402]  97.64 69.27 270 bottom
C417  0.1uF  [CC0402]  106.86 69.27 90 bottom
C418  10nF  [CC0402]  111.29 69.24 180 bottom
C419  0.1uF/16V  [CC0402]  103.58 68.83 90 bottom
C420  22uF/6.3V  [CC0603]  57.45 68.83 270 bottom
C421  0.1uF/16V  [CC0402]  85.85 68.78 270 bottom
C422  0.1uF  [CC0402]  101.68 68.58 180 bottom
C423  22uF/6.3V  [CC0603]  30.08 68.45 90 bottom
C424  22uF/6.3V  [CC0603]  90.22 68.15 0 bottom
C425  22uF/6.3V  [CC0603]  91.53 68.15 0 bottom
C426  22uF/6.3V  [CC0603]  92.87 68.15 0 bottom
C427  22uF/6.3V  [CC0603]  94.21 68.15 0 bottom
C428  22uF/6.3V  [CC0603]  95.53 68.15 0 bottom
C429  0.1uF/16V  [CC0402]  85.8 67.79 270 bottom
C430  1uF  [CC0402]  97.79 67.69 270 bottom
C431  0.1uF  [CC0402]  71.81 67.54 90 bottom
C432  0.1uF/16V  [CC0402]  100.8 67.51 0 bottom
C433  1uF/6.3V  [CC0402]  111.34 67.37 180 bottom
C434  0.1uF/16V  [CC0402]  112.28 67.37 180 bottom
C435  0.1uF/16V  [CC0402_22X22_8OCT]  193.59 53.61 180 bottom
C436  0.1uF/16V  [CC0402_22X22_8OCT]  194.59 53.61 180 bottom
C437  0.1uF/16V  [CC0402_22X22_8OCT]  197.59 53.61 180 bottom
C438  0.1uF/16V  [CC0402_22X22_8OCT]  198.59 53.61 180 bottom
C439  22uF/6.3V  [CC0603]  30.08 67.06 90 bottom
C440  0.1uF  [CC0402]  115.32 66.8 90 bottom
C441  0.1uF  [CC0402]  102.49 67.03 90 bottom
C442  0.1uF/16V  [CC0402]  32.81 66.72 90 bottom
C443  0.1uF/16V  [CC0402]  172.19 65.48 180 bottom
C444  0.1uF/16V  [CC0402]  79.53 66.67 180 bottom
C445  0.1uF/16V  [CC0402]  172.32 54.03 180 bottom
C446  0.1uF/16V  [CC0402]  85.22 66.6 270 bottom
C447  0.1uF  [CC0402]  99.18 66.57 0 bottom
C448  22uF/6.3V  [CC0603]  90.58 65.94 90 bottom
C449  22uF/6.3V  [CC0603]  96.72 65.91 270 bottom
C450  10nF/50V  [CC0402]  32.46 65.86 90 bottom
C452  0.1uF/16V  [CC0402_22X22_8OCT]  195.09 52.11 90 bottom
C453  0.1uF/16V  [CC0402_22X22_8OCT]  197.09 52.11 270 bottom
C454  0.1uF  [CC0402]  72.01 69.42 90 bottom
C455  0.1uF  [CC0402]  115.32 65.53 90 bottom
C456  0.1uF/16V  [CC0402]  107.26 65.49 270 bottom
C457  0.1uF  [CC0402]  105.92 66.9 270 bottom
C458  0.1uF/16V  [CC0402]  100.58 65.48 90 bottom
C459  22uF/6.3V  [CC0603]  30.08 65.53 90 bottom
C460  22uF/6.3V  [CC0603]  90.78 64.39 90 bottom
C461  22uF/6.3V  [CC0603]  97.33 64.39 270 bottom
C462  0.1uF  [CC0402]  115.32 64.13 90 bottom
C463  0.1uF/16V  [CC0402]  51.48 64.31 270 bottom
C464  0.1uF/16V  [CC0402]  172.24 62.92 270 bottom
C465  0.1uF/16V  [CC0402]  84.73 64.02 270 bottom
C466  0.1uF/16V  [CC0402]  82.75 64.01 270 bottom
C467  22uF/6.3V  [CC0603]  30.08 64.19 90 bottom
C468  0.1uF/16V  [CC0402]  78.08 63.83 0 bottom
C469  0.1uF/16V  [CC0402]  204.61 100.55 90 top
C470  0.1uF/16V  [CC0402]  79.2 63.35 180 bottom
C471  0.1uF/16V  [CC0402]  80.11 63.35 180 bottom
C472  0.1uF  [CC0402]  115.32 62.86 90 bottom
C473  0.1uF/16V  [CC0402]  30.48 62.96 90 bottom
C474  10nF/50V  [CC0402]  55.49 62.01 180 bottom
C475  0.1uF/16V  [CC0402]  56.48 62.01 180 bottom
C476  22uF/6.3V  [CC0603]  78.87 61.69 270 bottom
C477  0.1uF/16V  [CC0402_22X22_8OCT]  189.59 47.61 0 bottom
C478  0.1uF/16V  [CC0402_22X22_8OCT]  202.59 47.61 0 bottom
C479  0.1uF/16V  [CC0402_22X22_8OCT]  188.59 47.61 180 bottom
C480  0.1uF/16V  [CC0402_22X22_8OCT]  203.59 47.61 180 bottom
C481  0.1uF/16V  [CC0402]  91.82 60.82 270 bottom
C482  0.1uF/16V  [CC0402]  95.75 60.66 180 bottom
C483  22uF/6.3V  [CC0603]  29.41 61.8 90 bottom
C484  10nF/50V  [CC0402]  49.14 60.45 270 bottom
C485  22uF/6.3V  [CC0603]  78.87 60.35 270 bottom
C486  0.1uF/16V  [CC0402]  50.55 59.92 180 bottom
C487  0.1uF/16V  [CC0402]  53.89 59.8 180 bottom
C488  22uF/6.3V  [CC0603]  78.87 59 270 bottom
C489  10nF  [CC0402]  49.02 58.88 90 bottom
C490  10nF  [CC0402]  37.9 58.8 90 bottom
C491  10nF/50V  [CC0402]  47.44 58.4 180 bottom
C492  0.1uF/16V  [CC0402]  96.2 57.86 0 bottom
C493  0.1uF/16V  [CC0402]  93.4 57.65 270 bottom
C494  22uF/6.3V  [CC0603]  78.87 57.63 270 bottom
C495  0.1uF/16V  [CC0402]  91.98 57.18 0 bottom
C496  0.1uF/16V  [CC0402]  93.4 56.76 270 bottom
C497  0.1uF/16V  [CC0402]  96.65 56.45 90 bottom
C498  22uF/6.3V  [CC0603]  78.87 56.29 270 bottom
C499  0.1uF/16V  [CC0402]  115.32 53.29 0 bottom
C500  22uF/6.3V  [CC0603]  166.57 41 90 bottom
C501  22uF/6.3V  [CC0603]  92.46 51.92 90 bottom
C502  0.1uF/16V  [CC0402]  167.08 39.78 90 bottom
C503  22uF/6.3V  [CC0603]  96.01 50.76 270 bottom
C504  22uF/6.3V  [CC0603]  92.46 50.59 270 bottom
C505  0.1uF/16V  [CC0402]  168.99 39.78 270 bottom
C506  22uF/6.3V  [CC0603]  92.46 49.28 90 bottom
C507  22uF/6.3V  [CC0603]  169.6 41.02 270 bottom
C508  0.1uF/16V  [CC0402]  117.68 48.84 90 bottom
C509  0.1uF/16V  [CC0402]  113.44 48.08 90 bottom
C510  0.1uF/16V  [CC0402]  90.43 47.32 90 bottom
C511  1uF/6.3V  [CC0402]  90.43 46.43 90 bottom
C512  10uF/6.3V  [CC0402]  90.43 45.54 90 bottom
C513  10pF  [CC0402]  173.81 32.1 0 bottom
C514  1uF/6.3V  [CC0402]  174.6 36.07 0 bottom
C515  0.1uF/16V  [CC0402]  115.39 42.55 270 bottom
C516  10uF/6.3V  [CC0402]  174.62 21.69 0 bottom
C517  0.1uF/16V  [CC0402]  174.75 18.41 90 bottom
C518  0.1uF/16V  [CC0402]  45.19 39.52 90 bottom
C519  0.1uF/16V  [CC0402]  45.19 38.58 90 bottom
C520  10uF/6.3V  [CC0402]  41.73 38.09 0 bottom
C521  10uF/6.3V  [CC0402]  42.69 38.09 0 bottom
C522  10uF/6.3V  [CC0402]  90.88 37.95 90 bottom
C523  10uF/6.3V  [CC0402]  53.02 37.16 0 bottom
C524  10uF/6.3V  [CC0402]  53.92 37.16 0 bottom
C525  10nF/50V  [CC0402]  57 37.08 90 bottom
C526  1uF/6.3V  [CC0402]  90.88 37.06 90 bottom
C527  10uF/6.3V  [CC0402]  30.03 37 180 bottom
C528  10uF/6.3V  [CC0402]  30.97 37 180 bottom
C529  0.1uF/16V  [CC0402]  90.88 36.17 90 bottom
C530  0.1uF/16V  [CC0402]  57 36.14 90 bottom
C531  22uF/6.3V  [CC0603]  73.75 35.39 0 bottom
C532  22uF/6.3V  [CC0603]  75.14 35.39 0 bottom
C533  22uF/6.3V  [CC0603]  76.54 35.39 0 bottom
C534  22uF/6.3V  [CC0603]  77.94 35.39 0 bottom
C535  22uF/6.3V  [CC0603]  79.33 35.39 0 bottom
C536  22uF/6.3V  [CC0603]  80.73 35.39 0 bottom
C537  22uF/6.3V  [CC0603]  82.13 35.39 0 bottom
C538  22uF/6.3V  [CC0603]  83.53 35.39 0 bottom
C539  10nF/50V  [CC0402]  57 35.18 90 bottom
C540  0.1uF/16V  [CC0402]  84.68 35.09 180 bottom
C541  10uF/6.3V  [CC0402]  45.05 34.6 180 bottom
C542  10uF/6.3V  [CC0402]  45.99 34.6 180 bottom
C543  10uF/6.3V  [CC0402]  46.96 34.6 180 bottom
C544  0.1uF/16V  [CC0402]  182.8 19.08 270 bottom
C545  10uF/6.3V  [CC0402]  101.84 34.01 180 top
C546  22uF/6.3V  [CC0603]  104.55 33.9 0 bottom
C547  22uF/6.3V  [CC0603]  102.68 26.17 180 bottom
C548  22uF/6.3V  [CC0603]  103.12 33.9 0 bottom
C549  1uF/6.3V  [CC0402]  57 34.24 90 bottom
C550  10uF/6.3V  [CC0402]  31.35 34.19 180 bottom
C551  10uF/6.3V  [CC0402]  32.29 34.19 180 bottom
C552  10uF/6.3V  [CC0402]  33.23 34.19 180 bottom
C553  100uF/6.3V  [CC1206]  69.67 33.99 0 bottom
C554  100uF/6.3V  [CC1206]  71.86 34.09 0 bottom
C555  47uF/6.3V  [CC0805]  106.25 34.05 0 bottom
C556  47uF/6.3V  [CC0805]  105.96 26.02 180 bottom
C557  100uF/6.3V  [CC1206]  108.13 25.93 180 bottom
C558  100uF/6.3V  [CC1206]  108.41 33.76 0 bottom
C559  100uF/6.3V  [CC1206]  110.69 33.76 0 bottom
C560  100uF/6.3V  [CC1206]  112.98 33.76 0 bottom
C561  22uF/6.3V  [CC0603]  66.48 33.69 0 bottom
C562  22uF/6.3V  [CC0603]  67.88 33.69 0 bottom
C563  0.1uF/16V  [CC0402]  65.3 33.32 180 bottom
C564  1nF  [CC0402]  39.9 33.28 270 bottom
C565  22uF/6.3V  [CC0603]  56.48 33.07 90 bottom
C566  10nF/50V  [CC0402]  38.51 31.93 180 bottom
C567  0.1uF/16V  [CC0402]  197.07 15.03 90 bottom
C568  22uF/6.3V  [CC0603]  35.93 31.42 0 bottom
C569  22uF/6.3V  [CC0603]  37.29 31.42 0 bottom
C570  1uF/6.3V  [CC0402]  197.07 14.17 90 bottom
C571  1uF/6.3V  [CC0402]  157.06 70.52 270 bottom
C572  22uF/6.3V  [CC0603]  56.48 30.38 90 bottom
C573  0.1uF/16V  [CC0402]  150.5 17.27 180 bottom
C574  10uF/6.3V  [CC0402]  37.09 29.47 90 bottom
C575  10uF/6.3V  [CC0402]  37.09 28.55 90 bottom
C576  100uF/6.3V  [CC1206]  71.92 28 180 bottom
C577  100uF/6.3V  [CC1206]  74.08 28 180 bottom
C578  100uF/6.3V  [CC1206]  76.24 28 180 bottom
C579  100uF/6.3V  [CC1206]  78.4 28 180 bottom
C580  100uF/6.3V  [CC1206]  80.49 28 180 bottom
C581  100uF/6.3V  [CC1206]  82.63 28 180 bottom
C582  47uF/6.3V  [CC0805]  45.46 28 0 bottom
C583  47uF/6.3V  [CC0805]  47.32 27.99 0 bottom
C584  47uF/6.3V  [CC0805]  49.21 27.99 0 bottom
C585  47uF/16V  [CC1210]  152.65 18.16 180 bottom
C586  100uF/6.3V  [CC1206]  51.23 27.91 180 bottom
C587  100uF/6.3V  [CC1206]  53.37 27.91 180 bottom
C588  1nF  [CC0402]  38.05 26.65 270 bottom
C589  10uF/6.3V  [CC0402]  41.5 25.29 270 bottom
C590  0.1uF/16V  [CC0402]  196.06 8.1 270 bottom
C591  47uF/16V  [CC1210]  155.95 18.16 180 bottom
C592  0.1uF/16V  [CC0402]  41.5 24.36 270 bottom
C593  0.22uF  [CC0805]  120.04 21.45 90 bottom
C594  0.22uF  [CC0805]  54.46 22.66 180 bottom
C595  0.1uF/16V  [CC0402]  60.81 22.58 90 bottom
C596  1uF/6.3V  [CC0402]  32.44 22.02 180 bottom
C597  0.22uF/16V  [CC0402]  60.81 21.59 90 bottom
C598  22uF/16V  [CC0805]  49.48 21.11 180 bottom
C599  22uF/16V  [CC0805]  51.38 21.11 180 bottom
C600  22uF/16V  [CC0805]  65.13 20.24 0 bottom
C601  1uF  [CC0402]  185.67 8.89 0 top
C602  47uF/16V  [CC1210]  42.81 15.88 180 bottom
C603  47uF/16V  [CC1210]  46.07 15.88 180 bottom
C604  @10pF  [CC0402]  182.93 15.33 270 bottom
C605  @10pF  [CC0402]  184.81 15.33 90 bottom
C606  22uF/16V  [CC0805]  81.97 14.61 90 bottom
C607  0.01uF  [CC0402]  86.77 14.58 180 bottom
C608  0.1uF/25V  [CC0402]  152.14 41.48 90 bottom
C609  1uF/6.3V  [CC0402]  159.82 13.22 0 bottom
C610  0.1uF/16V  [CC0402]  160.76 13.22 0 bottom
C611  10nF/50V  [CC0402]  161.69 13.22 180 bottom
C612  47uF/6.3V  [CC0805]  158.3 12.8 0 bottom
C613  47uF  [CC0805]  33.05 12.45 270 bottom
C614  22uF/16V  [CC0805]  53.44 12.37 270 bottom
C615  100uF/6.3V  [CC1206]  81.48 20.98 0 bottom
C616  100uF/6.3V  [CC1206]  85.85 12.45 270 top
C619  0.22uF  [CC0402]  145.84 10.92 180 bottom
C620  0.22uF  [CC0402]  146.86 10.92 180 bottom
C621  0.22uF  [CC0402]  147.84 10.92 180 bottom
C622  0.22uF  [CC0402]  148.86 10.92 180 bottom
C623  0.22uF  [CC0402]  154.18 12.06 180 bottom
C624  0.22uF  [CC0402]  155.45 12.06 180 bottom
C625  10nF/50V  [CC0402]  53.26 10.06 90 bottom
C626  @0.1uF/16V  [CC0402]  153.27 36.63 0 bottom
C627  47uF/6.3V  [CC0805]  168.02 9.53 90 bottom
C628  3300pF  [CC0402]  78.05 9.12 180 bottom
C629  1uF/6.3V  [CC0402]  167.1 8.01 90 bottom
C630  0.22uF/16V  [CC0402]  63.16 7.96 180 bottom
C631  0.1uF/16V  [CC0402]  167.1 7.07 90 bottom
C632  0.1uF/16V  [CC0402]  81.61 6.94 0 bottom
C633  0.01uF  [CC0402]  70.11 6.87 90 bottom
C634  1nF/50V  [CC0402]  167.1 6.13 90 bottom
C635  1uF  [CC0402]  70.11 5.91 270 bottom
C636  10pF/50V  [CC0402]  149.99 32.72 270 bottom
C637  0.1uF  [CC0402]  16.03 4.75 270 bottom
C638  47uF  [CC0805]  42.72 3.4 90 bottom
C639  0.1uF  [CC0402]  45.31 3.4 180 bottom
C640  0.1uF/16V  [CC0402]  205.11 115.52 270 top
C643  0.22uF  [CC0402]  133.1 90.02 270 top
C644  0.22uF  [CC0402]  133.1 91.34 270 top
C647  0.1uF  [CC0402]  168.78 111.63 90 bottom
C648  0.1uF  [CC0402]  168.78 108.46 270 bottom
C649  27pF(1%)  [CC0402]  142.37 77.09 270 top
C650  27pF(1%)  [CC0402]  144.65 77.09 270 top
C651  0.1uF/16V  [CC0402]  135.64 102.23 0 top
C652  100uF/6.3V  [CC1206]  67.44 14.71 270 top
C664  0.1uF  [CC0402]  147.83 84.96 270 top
C665  0.1uF  [CC0402]  147.83 83.82 270 top
C701  100uF/6.3V  [CC1206]  67.26 20.17 0 bottom
C702  100uF/6.3V  [CC1206]  111.56 15.65 0 top
C703  0.01uF  [CC0402]  132.84 86.31 270 top
C704  0.01uF  [CC0402]  132.84 87.63 270 top
C707  22uF/16V  [CC0805]  178.9 99.15 180 top
C708  22uF/16V  [CC0805]  172.97 99.65 0 top
C841  0.039uF  [CC0603]  140.21 80.9 0 top
C900  100uF/6.3V  [CC1206]  165.17 104.97 90 top
C901  100uF6.3V  [CC1206]  157.68 56.71 180 top
C902  100uF6.3V  [CC1206]  149.73 56.62 180 top
C903  220uF/4V  [CAP_6D4_2SP_4D3W7D3L2D1H]  164.03 54.61 180 top
C904  100uF/6.3V  [CC1206]  165.14 48.61 90 top
C905  100uF/6.3V  [CC1206]  108.91 2.41 90 top
C906  560uF/2V  [CAP_6D4_2SP_4D3W7D3L4D3H]  111.63 24.64 90 top
C907  220uF/4V  [CAP_6D4_2SP_4D3W7D3L2D1H]  165.51 44.93 180 top
C908  0.1uF/16V  [CC0402]  26.92 55.63 270 bottom
C909  0.1uF/16V  [CC0402]  30.86 57.28 180 bottom
C910  0.1uF/16V  [CC0402]  100.33 119.25 270 top
C911  0.1uF/16V  [CC0402]  106.6 119.33 270 bottom
C912  0.1uF/16V  [CC0402]  111.89 108.08 90 top
C913  0.1uF/16V  [CC0402]  174.75 17.4 90 bottom
C914  0.1uF/16V  [CC0402]  178.31 18.03 0 bottom
C915  0.1uF/16V  [CC0402]  178.18 21.21 180 bottom
C925  0.1uF/16V  [CC0402]  146.3 92.58 0 bottom
C926  0.1uF/16V  [CC0402]  143.76 93.34 0 bottom
C927  0.1uF/16V  [CC0402]  142.11 94.23 270 bottom
C928  0.1uF/16V  [CC0402]  140.97 84.84 180 bottom
C929  0.1uF/16V  [CC0402]  144.78 93.34 0 bottom
C930  1uF/6.3V  [CC0402]  140.97 93.22 90 bottom
C931  10uF/6.3V  [CC0402]  136.4 87.63 180 bottom
C933  0.1uF/16V  [CC0402]  141.99 84.84 180 bottom
C934  0.1uF/16V  [CC0402]  139.32 84.4 270 bottom
C935  0.1uF/16V  [CC0402]  136.4 84.96 180 bottom
C936  0.1uF/16V  [CC0402]  138.94 93.22 270 bottom
C937  0.1uF/16V  [CC0402]  138.94 92.2 270 bottom
C938  1uF/6.3V  [CC0402]  145.16 89.66 270 bottom
C939  10uF/6.3V  [CC0402]  145.16 90.68 270 bottom
C941  0.1uF/16V  [CC0402]  138.3 85.85 180 bottom
C942  0.1uF/16V  [CC0402]  145.29 86.87 180 bottom
C943  0.1uF/16V  [CC0402]  143 84.84 0 bottom
C944  1uF/6.3V  [CC0402]  144.53 84.33 90 bottom
C945  10uF/6.3V  [CC0402]  139.32 85.85 180 bottom
C959  47uF/6.3V  [CC0805]  136.27 82.04 0 bottom
C960  47uF/6.3V  [CC0805]  142.88 88.27 180 bottom
C961  47uF/6.3V  [CC0805]  147.32 94.61 90 bottom
C963  1uF/6.3V  [CC0402]  136.65 102.23 0 top
C964  0.1uF/16V  [CC0402]  36.7 109.86 0 bottom
C965  560uF  [CAP_6D1_2SP_4D3W7D3L2D8H_AC]  132.86 56.24 180 top
C966  560uF  [CAP_6D1_2SP_4D3W7D3L2D8H_AC]  134.87 56.08 180 bottom
C967  47uF  [CC0603]  118.77 68.3 180 top
C968  47uF  [CC0603]  120.17 68.3 180 top
C969  47uF  [CC0603]  131.5 63.12 180 top
C970  47uF  [CC0603]  122.83 58.01 0 top
C971  47uF  [CC0603]  103.5 64.31 270 bottom
C972  47uF  [CC0603]  132.74 51.56 270 bottom
C973  47uF  [CC0603]  132.74 52.96 270 bottom
C974  1uF  [CC0402]  125.98 92.96 180 top
C975  47uF  [CC0603]  126.59 58.06 0 top
C976  47uF  [CC0603]  100.66 64.31 90 bottom
CONN1  MCUS-05BR-SD01  [USB_D65_5SP_4D96W7D51L2D71H]  184.12 121.92 0 top
CONN2  HXSPH2.54-S-S-03-G/F  [CONN_2D54_3SP_4W7D62L9D3H_1]  55.68 119.25 0 top
CONN3  21N21040-08M00B-01G-2.8-C-10  [CONNM_1D27X4D1_2X4SP_3D8H]  46.39 118.67 180 top
CONN4  BTB_FEMALE_SMD60  [CONNF_D5X5D728_2X30SP_21D3W]  32.82 120.14 180 top
CONN5  21N22564-10MOPB-01G-6-V10-C-10  [M_CONN_2D54X5D35_2X5SP]  163.4 95 180 top
CONN6  MSATA_FEMALE_52P_G2  [CONNF_D8_2X26SP_29D9W8D2L5D6H]  191.55 84.9 180 top
CONN7  1782A1BF40A  [CONN_D5X8D2_260SP_73W24D5L]  37.28 69.58 90 top
CONN8  1782A1BF80A  [CONN_D5X8D2_260SP_73W24D5L_1]  49.28 69.58 90 top
CONN9  PHED-SS010G1ABONE-B140  [CONN_2D54X5D61_2X5SP_12D7W5L]  199.85 7.52 180 top
CONN11  BTB_FEMALE_SMD60  [CONNF_D5X5D728_2X30SP_21D3W]  24.89 3.81 0 top
CONN12  HXSPH2.54-S-S-03-G/F  [CONN_2D54_3SP_4W7D62L9D3H_1]  117.07 5.42 180 top
CONN13  @213BAAA42FA  [CONN_D5X7D55_75SP_21D9W4D2H]  198.05 109.77 180 bottom
CONN14  BMM CONN  [SOCKET_SODIMM_D6X8D2_204SP_TB]  17.55 47.03 270 bottom
CONN15  CONN_WAFER_MALE_8PX1R_G2  [CONN_1D_8SP_10W4D25L]  202.74 10.87 270 bottom
CONN16  BTB_MALE_SMD120  [CONNM_D5X5D32_2X60SP_COMBO_2]  143.86 3.84 0 bottom
CONN17  HXSPH2.54-S-S-03-G/F  [CONN_2D54_3SP_4W7D62L9D3H_1]  138.43 119.52 180 top
CONN18  PHE6T0-104S4L6.0-3.3-5.0  [CONNM_2D54X2D5_2X2SP_10D16W9D8H]  203.8 108.5 90 top
D1  1N4148W  [DIOSCHTKY_2SP_1D6WX2D7L_AC]  102.79 5.38 180 bottom
H1  @SCREW_8_2  [MTH_276C138D_8DP]  53.52 110.12 0 top
H2  @SCREW_8_2  [MTH_276C138D_8DP]  176.4 110.12 0 top
H7  @SCREW_8_2  [MTH_276C138D_8DP]  9.6 5 0 top
H8  @SCREW_8_2  [MTH_276C138D_8DP]  176.4 5 0 top
H9  @SCREW_8_2  [MTH_276C138D_8DP]  90.7 5 0 top
HS1  @SILVER_0P605275  [HSINK_60D_4DP_70WL13D3H]  94.47 71.5 270 top
HSB1  @Heatsink_Bracket  [HSINK_60D_4DPNP_71W70L_1]  94.47 71.5 180 bottom
L1  100MHz  [LC0603]  169.19 114.73 0 top
L2  4.7uH / 6.5A  [CHOKE_6D05_2SP_6D6WL5H]  117.88 113.12 90 top
L3  100MHz  [LC0603]  154.94 117.86 270 top
L4  100MHz  [LC0805]  113.79 106.4 270 top
L5  100MHz  [LC0805]  190.73 38.07 0 top
L6  0.025ohm 6A  [LC0805]  205.61 75.33 270 top
L7  100MHz/5A/0.02ohm  [LC0603]  124.59 81.66 180 top
L8  100MHz/5A/ 0.01ohm  [LC0603]  123.11 80.06 180 top
L9  100MHz/6A/0.007ohm  [LC0603]  121.81 76.68 270 top
L10  100MHz/6A/0.007ohm  [LC0603]  132.31 59.39 270 top
L11  4.7uH/6.5A  [CHOKE_6D05_2SP_6D6WL5H]  161.01 37.72 90 top
L12  @100MHz  [LC0805]  169.11 28.47 0 top
L13  2.2uH/8A  [CHOKE_6D05_2SP_6D6WL5H]  166.3 65.96 270 top
L14  1uH/16A  [IND_5D1_2SP_7D1WL4D2H]  59.46 29.53 90 top
L15  150nH 0.00029ohm  [IND_7D7_2SP_7D8W10D2L]  89.28 28.96 270 top
L16  150nH 0.00029ohm  [IND_7D7_2SP_7D8W10D2L]  71.76 28.71 90 top
L17  150nH 0.00029ohm  [IND_7D7_2SP_7D8W10D2L]  118.48 29.09 180 top
L18  2.2uH/8A  [CHOKE_6D05_2SP_6D6WL5H]  22.84 26.61 90 top
L19  100MHz  [LC0805]  165.16 75.02 180 top
L20  4.7uH/6.5A  [CHOKE_6D05_2SP_6D6WL5H]  152.51 47.87 90 top
L21  100MHz  [LC0805]  22.43 18.82 0 top
L22  120ohm  [LC0805]  7.05 16.8 90 top
L23  BEAD/10MHz/10A  [BEAD_3D58_2SP_3D05W4D06L2D62H]  162.03 16.43 90 top
L24  0.33uH  [CHOKE_3D7_2SP_4W4D5L2H]  37.79 15.41 0 top
L25  0.012ohm  [LC1206]  87.17 15.11 270 top
L26  0.012ohm  [LC1206]  120.62 11.76 270 top
L27  100MHz  [LC0805]  144.22 41.1 270 top
L28  100MHz (3A/40mohm)  [LC0603]  161.54 106.17 180 top
L29  @100MHz (3A/40mohm)  [LC0603]  160.02 106.17 180 top
L30  100MHz  [LC0603]  112.15 76.4 270 bottom
L31  100MHz  [LC0603]  96.65 74.65 180 bottom
L32  100MHz/7.5A/4mohm  [LC0603]  117.98 73.79 180 bottom
L33  100MHz  [LC0603]  103.73 72.4 0 bottom
L34  100MHz  [LC0603]  99.44 72.06 0 bottom
L35  100MHz  [LC0603]  113.29 70.04 270 bottom
L36  100MHz  [LC0603]  41.81 26.47 90 bottom
L37  120ohm  [LC0805]  167.89 11.68 270 bottom
L41  100MHz  [LC0603]  108.03 5.03 0 top
L42  100MHz  [LC0603]  108.41 9.47 270 top
L49  0.012ohm  [LC1206]  175.37 99.41 180 top
L50  100MHz  [LC0805]  163.54 27.5 0 top
LED1  LED1_1  [LED_1D5_2SP_D8W1D6LD6H_AC]  192.28 119.29 0 top
LED2  LED1_1  [LED_1D5_2SP_D8W1D6LD6H_AC]  194.06 119.29 0 top
LED3  LED1_1  [LED_1D5_2SP_D8W1D6LD6H_AC]  197.62 119.29 0 top
LED4  LED1_1  [LED_1D5_2SP_D8W1D6LD6H_AC]  199.02 119.29 0 top
LED5  LED1_1  [LED_1D5_2SP_D8W1D6LD6H_AC]  200.67 119.29 0 top
LED6  LED1_1  [LED_1D5_2SP_D8W1D6LD6H_AC]  202.06 119.29 0 top
LED7  LED1_1  [LED_1D5_2SP_D8W1D6LD6H_AC]  203.46 119.29 0 top
LED8  LED1_1  [LED_1D5_2SP_D8W1D6LD6H_AC]  205.11 119.29 0 top
LED9  LED1_1  [LED_1D5_2SP_D8W1D6LD6H_AC]  206.51 119.29 0 top
LED10  LED1_1  [LED_1D5_2SP_D8W1D6LD6H_AC]  190.51 119.24 0 top
LED11  LED1_1  [LED_1D5_2SP_D8W1D6LD6H_AC]  165.23 78.87 90 top
LED13  LED1_1  [LED_1D5_2SP_D8W1D6LD6H_AC]  182.47 14.58 180 top
LED14  LED1_1  [LED_1D5_2SP_D8W1D6LD6H_AC]  185.26 14.58 180 top
LED15  LED1_1  [LED_1D5_2SP_D8W1D6LD6H_AC]  187.04 14.58 180 top
LED16  LED1_1  [LED_1D5_2SP_D8W1D6LD6H_AC]  188.82 14.58 180 top
LED17  LED1_1  [LED_1D5_2SP_D8W1D6LD6H_AC]  190.6 14.58 180 top
LED18  LED1_1  [LED_1D5_2SP_D8W1D6LD6H_AC]  132.72 80.29 180 top
LED19  LED2_1  [LED_1D65XD85_4SP_1D25W1D6L_AC]  197.89 75.55 0 top
NOREF  -  []  208.05 109.77 0 top
NOREF#2  -  []  90.7 5 0 top
NOREF#3  -  []  124.47 101.5 0 top
NOREF#4  -  []  124.47 41.5 0 top
NOREF#5  -  []  198.05 31.52 0 top
NOREF#6  -  []  163.4 98.81 0 top
NOREF#7  -  []  184.6 106.5 0 top
NOREF#8  -  []  13.51 163.5 0 top
NOREF#9  -  []  196.8 83.5 0 top
NOREF#10  -  []  37.28 103.98 0 top
NOREF#11  -  []  190.9 95 0 top
NOREF#12  -  [unnamed#2]  3.02 113.49 90 top
NOREF#13  -  [unnamed#2]  3.99 119.58 0 top
NOREF#14  -  []  176.4 110.12 0 top
NOREF#15  -  []  179.45 36.85 0 top
NOREF#16  -  []  22.08 9.34 0 top
NOREF#17  -  []  176.4 110.12 0 top
NOREF#18  -  [unnamed#2]  26.39 14.61 90 top
NOREF#19  -  []  35.63 114.61 0 top
NOREF#20  -  []  210 123.5 0 top
NOREF#21  -  []  22.08 9.34 0 top
NOREF#22  -  []  208.05 109.77 0 top
NOREF#23  -  []  9.6 5 0 top
NOREF#24  -  []  129.47 36.5 0 top
NOREF#25  -  []  17.55 13.63 0 top
NOREF#26  -  []  53.52 110.12 0 top
NOREF#27  -  []  127.94 23.16 0 top
NOREF#28  -  []  198.05 31.52 0 top
NOREF#29  -  []  179.05 84.9 0 top
NOREF#30  -  []  64.47 101.5 0 top
NOREF#31  -  []  196.8 104.23 0 top
NOREF#32  -  []  0 0 0 top
NOREF#33  -  []  179.45 36.85 0 top
NOREF#34  -  []  17.55 13.63 0 top
NOREF#35  -  []  125.32 3.84 0 top
NOREF#36  -  []  49.28 103.98 0 top
NOREF#37  -  []  9.6 5 0 top
NOREF#38  -  []  210 0 0 top
NOREF#39  -  []  190.9 95 0 top
NOREF#40  -  []  320.76 -38.48 0 top
NOREF#41  -  []  35.63 114.61 0 top
NOREF#42  -  []  506.73 -44.45 0 top
NOREF#43  -  [unnamed#2]  175.93 119.89 90 top
NOREF#44  -  []  158.8 106.5 0 top
NOREF#45  -  []  179.05 84.9 0 top
NOREF#46  -  []  124.47 101.5 0 top
NOREF#47  -  []  198.05 69.52 0 top
NOREF#48  -  []  49.28 103.98 0 top
NOREF#49  -  []  163.4 98.81 0 top
NOREF#50  -  []  203.65 36.85 0 top
NOREF#51  -  []  176.4 5 0 top
NOREF#52  -  []  125.32 3.84 0 top
NOREF#53  -  []  0 0 0 top
NOREF#54  -  [unnamed#2]  198.05 31.52 180 bottom
NOREF#55  -  [unnamed#2]  5.56 113.49 270 bottom
NOREF#56  -  [unnamed#2]  173.39 119.89 270 bottom
NOREF#57  -  [unnamed#2]  28.93 14.61 270 bottom
NOREF#58  -  [unnamed#2]  198.05 69.52 180 bottom
NUT1  NUT_1  [NUT_335C166D]  190.9 95 0 top
NUT2  NUT_1  [NUT_236C134D_3D2H]  179.45 36.85 0 top
NUT3  NUT_1  [NUT_236C134D_3D2H]  203.65 36.85 0 top
OSC1  50MHz+/-25ppm  [OSC_1D6X2D12_4SP_2D5W3D2L1DH]  166.49 119 180 top
OSC2  25MHz  [OSC_1D7X2D2_4SP_2D5W3D2L1D1H]  121.67 93.6 180 top
OSC4  25MHz  [OSC_1D6X2D12_4SP_2D5W3D2L1DH]  197.79 39.6 90 top
OSC5  25Mhz  [OSC_1D6X2D12_4SP_2D5W3D2LD75H]  122.97 65.02 180 top
OSC6  25MHz+/-10ppm  [OSC_1D6X2D12_4SP_2D5W3D2LD75H]  143.51 74.8 180 top
Q1  N-CH  [SOT23_1D9X2D2_3SP_1D3W2D92LGSD]  111.88 106.56 90 bottom
Q2  N-CH  [SOT23_1D9X2D2_3SP_1D3W2D92LGSD]  61.01 109.22 90 top
Q3  BAT54C  [SOT23_1D9X2D_3SP_1D3W2D95L1D15H]  3.95 107.24 270 top
Q4  N-CH  [SOT23_1D9X2D2_3SP_1D3W2D92LGSD]  72.62 100.5 0 top
Q5  N-CH  [SOT23_1D9X2D2_3SP_1D3W2D92LGSD]  165.35 84.46 180 top
Q6  2N7002  [SOT23_1D9X2D2_3SP_1D3W2D92LGSD]  98.12 6.22 270 top
Q7  BAT54C-7-F  [SOT23_1D9X2D_3SP_1D3W2D95L1D15H]  52.87 119.25 90 bottom
Q8  N-CH  [SOT23_3SP_GSD]  27.77 53.08 90 bottom
Q9  74AVCH1T45GW  [SOT363_D65_6SP_1D25W2L1D1H]  117.26 51.41 180 bottom
Q10  74AVCH1T45GW  [SOT363_D65_6SP_1D25W2L1D1H]  113.79 50.65 180 bottom
Q11  N-CH  [SOT23_3SP_GSD]  27.74 49.45 90 bottom
Q12  N-CH  [SOT23_3SP_GSD]  86.11 46.13 90 bottom
Q13  N-CH  [SOT23_3SP_GSD]  86.08 42.57 0 bottom
Q14  2N7002  [SOT23_1D9X2D2_3SP_1D3W2D92LGSD]  98.12 6.22 90 bottom
Q16  N-CH  [SOT23_3SP_GSD]  113.28 110.62 270 bottom
QFN1  IR3553MTRPBF  [QFN_D5_25SP_4W6L_IOR]  56.62 21.24 180 top
R4  10K  [RC0402]  90.17 117.39 0 top
R5  7.5K  [RC0402]  92.84 117.19 0 top
R6  10K  [RC0402]  61.37 116.38 0 top
R7  0  [RC0402]  69.57 115.4 90 top
R8  0  [RC0402]  73.58 115.39 90 top
R9  @1K  [RC0402]  82.85 115.34 90 top
R10  4.7K  [RC0402]  64.99 115.32 270 top
R11  @1K  [RC0402]  77.82 115.32 270 top
R12  0  [RC0402]  90.95 115.26 90 top
R13  0  [RC0402]  86.74 115.26 270 top
R14  4.7K  [RC0402]  69.57 114.46 270 top
R15  33  [RC0402]  73.58 114.43 90 top
R17  10K  [RC0402]  64.99 114.42 90 top
R18  0  [RC0402]  82.85 114.38 270 top
R19  0  [RC0402]  77.82 114.35 90 top
